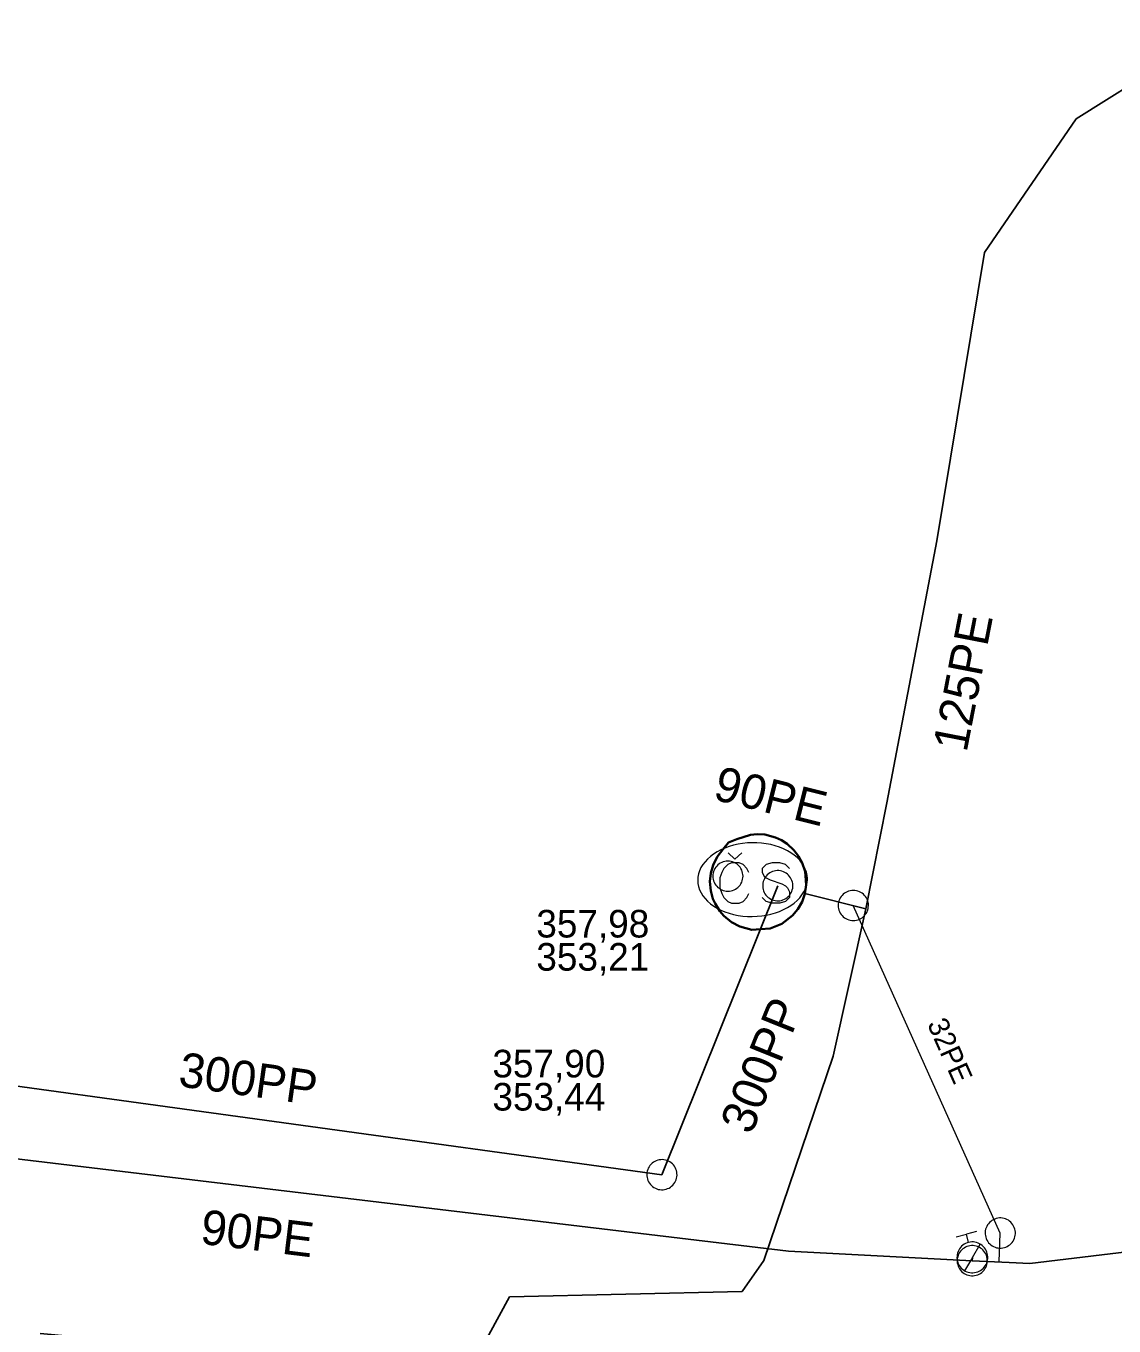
# Model space of a CAD drawing. Extents: x -741806 to -738704, y -1059275 to -1055387.
# Drawn here: x -740753.77 to -740722.25, y -1057687.05 to -1057649.38 of the extents above; entities that cross this region are included whole.
import ezdxf

# ---------------------------------------------------------------- set-up
doc = ezdxf.new("R2010")
doc.units = 0
doc.header["$LTSCALE"] = 0.4
for name, color, linetype, lineweight in [('11', 7, 'Continuous', 13), ('2', 7, 'Continuous', 25), ('21', 7, 'Continuous', 13), ('3', 7, 'Continuous', 13), ('45', 7, 'Continuous', 35), ('50', 7, 'Continuous', 13), ('51', 7, 'Continuous', 13), ('52', 7, 'Continuous', 25)]:
    doc.layers.add(name, color=color, linetype=linetype, lineweight=lineweight)
for name, color, linetype in [('5', 7, 'Continuous'), ('53', 7, 'Continuous'), ('54', 7, 'Continuous'), ('55', 7, 'Continuous')]:
    doc.layers.add(name, color=color, linetype=linetype)

msp = doc.modelspace()

# ---------------------------------------------------------------- linework, layer by layer
at = {"layer": '11'}
for q in [(-740733.428, -1057673.337), (-740733.036, -1057673.337)]:
    msp.add_line((-740733.232, -1057673.528), q, dxfattribs=at)
msp.add_lwpolyline([(-740731.135, -1057674.086), (-740731.143, -1057673.993), (-740731.163, -1057673.901), (-740731.194, -1057673.811), (-740731.237, -1057673.723), (-740731.292, -1057673.639), (-740731.357, -1057673.557), (-740731.432, -1057673.48), (-740731.517, -1057673.408), (-740731.612, -1057673.341), (-740731.714, -1057673.28), (-740731.824, -1057673.226), (-740731.941, -1057673.178), (-740732.064, -1057673.137), (-740732.192, -1057673.103), (-740732.324, -1057673.077), (-740732.459, -1057673.059), (-740732.596, -1057673.049), (-740732.734, -1057673.048), (-740732.872, -1057673.054), (-740733.009, -1057673.068), (-740733.143, -1057673.09), (-740733.274, -1057673.12), (-740733.402, -1057673.157), (-740733.524, -1057673.202), (-740733.64, -1057673.253), (-740733.749, -1057673.311), (-740733.85, -1057673.375), (-740733.943, -1057673.445), (-740734.027, -1057673.52), (-740734.1, -1057673.599), (-740734.164, -1057673.682), (-740734.216, -1057673.769), (-740734.257, -1057673.858), (-740734.287, -1057673.949), (-740734.305, -1057674.041), (-740734.311, -1057674.134), (-740734.305, -1057674.227), (-740734.286, -1057674.318), (-740734.257, -1057674.409), (-740734.215, -1057674.497), (-740734.162, -1057674.582), (-740734.099, -1057674.664), (-740734.025, -1057674.742), (-740733.941, -1057674.814), (-740733.848, -1057674.882), (-740733.746, -1057674.944), (-740733.637, -1057674.999), (-740733.521, -1057675.048), (-740733.399, -1057675.09), (-740733.271, -1057675.125), (-740733.14, -1057675.152), (-740733.005, -1057675.171), (-740732.868, -1057675.182), (-740732.731, -1057675.185), (-740732.593, -1057675.18), (-740732.456, -1057675.167), (-740732.321, -1057675.146), (-740732.189, -1057675.117), (-740732.061, -1057675.08), (-740731.938, -1057675.037), (-740731.822, -1057674.986), (-740731.711, -1057674.929), (-740731.609, -1057674.866), (-740731.515, -1057674.797), (-740731.43, -1057674.723), (-740731.355, -1057674.644), (-740731.29, -1057674.561), (-740731.236, -1057674.475), (-740731.193, -1057674.387), (-740731.162, -1057674.296), (-740731.143, -1057674.204), (-740731.135, -1057674.111)], close=True, dxfattribs=at)
for points in [[(-740732.828, -1057673.906), (-740732.884, -1057673.794), (-740732.996, -1057673.682), (-740733.108, -1057673.626), (-740733.33, -1057673.626), (-740733.439, -1057673.682), (-740733.551, -1057673.794), (-740733.615, -1057673.906), (-740733.671, -1057674.068), (-740733.671, -1057674.357), (-740733.615, -1057674.522), (-740733.551, -1057674.634), (-740733.439, -1057674.749), (-740733.33, -1057674.799), (-740733.108, -1057674.799), (-740732.996, -1057674.749), (-740732.884, -1057674.634), (-740732.828, -1057674.522)], [(-740731.655, -1057673.794), (-740731.767, -1057673.682), (-740731.932, -1057673.626), (-740732.156, -1057673.626), (-740732.324, -1057673.682), (-740732.442, -1057673.794), (-740732.442, -1057673.906), (-740732.389, -1057674.015), (-740732.324, -1057674.068), (-740732.21, -1057674.124), (-740731.876, -1057674.236), (-740731.767, -1057674.301), (-740731.711, -1057674.357), (-740731.655, -1057674.469), (-740731.655, -1057674.634), (-740731.767, -1057674.749), (-740731.932, -1057674.799), (-740732.156, -1057674.799), (-740732.324, -1057674.749), (-740732.442, -1057674.634)]]:
    msp.add_lwpolyline(points, dxfattribs=at)
at = {"layer": '2'}
for p, q in [((-740735.349, -1057682.666), (-740731.993, -1057674.294)), ((-740731.17, -1057674.524), (-740729.436, -1057674.959))]:
    msp.add_line(p, q, dxfattribs=at)
for points in [[(-740723.35, -1057652.071), (-740715.67, -1057647.25), (-740702.59, -1057629.575)], [(-740765.321, -1057634.66), (-740765.339, -1057637.145), (-740765.221, -1057649.531), (-740765.019, -1057662.11), (-740765.083, -1057671.477), (-740757.826, -1057679.575), (-740735.349, -1057682.666)], [(-740753.366, -1057687.272), (-740740.964, -1057688.405), (-740739.761, -1057686.21), (-740733.024, -1057686.05), (-740732.395, -1057685.151), (-740730.385, -1057679.235), (-740729.436, -1057674.959), (-740728.829, -1057671.892), (-740727.385, -1057664.297), (-740726.006, -1057655.95), (-740723.35, -1057652.071)]]:
    msp.add_lwpolyline(points, dxfattribs=at)
at = {"layer": '21'}
msp.add_lwpolyline([(-740725.581, -1057685.195), (-740725.546, -1057684.358), (-740729.804, -1057674.867)], dxfattribs=at)
at = {"layer": '3'}
for points in [[(-740732.999, -1057674.015), (-740733.002, -1057673.97), (-740733.009, -1057673.925), (-740733.021, -1057673.88), (-740733.037, -1057673.838), (-740733.058, -1057673.797), (-740733.083, -1057673.758), (-740733.112, -1057673.723), (-740733.144, -1057673.69), (-740733.18, -1057673.662), (-740733.218, -1057673.637), (-740733.259, -1057673.616), (-740733.302, -1057673.599), (-740733.346, -1057673.588), (-740733.391, -1057673.58), (-740733.437, -1057673.578), (-740733.483, -1057673.58), (-740733.528, -1057673.588), (-740733.572, -1057673.599), (-740733.615, -1057673.616), (-740733.656, -1057673.637), (-740733.694, -1057673.662), (-740733.729, -1057673.69), (-740733.762, -1057673.723), (-740733.791, -1057673.758), (-740733.816, -1057673.797), (-740733.836, -1057673.838), (-740733.853, -1057673.88), (-740733.865, -1057673.925), (-740733.872, -1057673.97), (-740733.874, -1057674.016), (-740733.872, -1057674.061), (-740733.865, -1057674.106), (-740733.853, -1057674.151), (-740733.836, -1057674.194), (-740733.816, -1057674.234), (-740733.791, -1057674.273), (-740733.762, -1057674.308), (-740733.729, -1057674.341), (-740733.694, -1057674.369), (-740733.656, -1057674.394), (-740733.615, -1057674.415), (-740733.572, -1057674.432), (-740733.528, -1057674.444), (-740733.483, -1057674.451), (-740733.437, -1057674.453), (-740733.391, -1057674.451), (-740733.346, -1057674.444), (-740733.302, -1057674.432), (-740733.259, -1057674.415), (-740733.218, -1057674.394), (-740733.18, -1057674.369), (-740733.144, -1057674.341), (-740733.112, -1057674.308), (-740733.083, -1057674.273), (-740733.058, -1057674.234), (-740733.037, -1057674.193), (-740733.021, -1057674.151), (-740733.009, -1057674.106), (-740733.002, -1057674.061), (-740732.999, -1057674.016)], [(-740731.829, -1057673.887), (-740731.872, -1057673.873), (-740731.916, -1057673.863), (-740731.963, -1057673.857), (-740732.007, -1057673.857), (-740732.053, -1057673.861), (-740732.099, -1057673.869), (-740732.142, -1057673.883), (-740732.185, -1057673.901), (-740732.224, -1057673.924), (-740732.261, -1057673.95), (-740732.296, -1057673.98), (-740732.328, -1057674.014), (-740732.355, -1057674.05), (-740732.379, -1057674.089), (-740732.398, -1057674.131), (-740732.413, -1057674.175), (-740732.422, -1057674.219), (-740732.428, -1057674.264), (-740732.429, -1057674.31), (-740732.424, -1057674.356), (-740732.415, -1057674.401), (-740732.402, -1057674.444), (-740732.384, -1057674.487), (-740732.362, -1057674.527), (-740732.335, -1057674.564), (-740732.305, -1057674.598), (-740732.272, -1057674.63), (-740732.235, -1057674.657), (-740732.196, -1057674.681), (-740732.154, -1057674.7), (-740732.111, -1057674.715), (-740732.067, -1057674.725), (-740732.021, -1057674.73), (-740731.974, -1057674.731), (-740731.93, -1057674.727), (-740731.884, -1057674.718), (-740731.841, -1057674.704), (-740731.798, -1057674.686), (-740731.759, -1057674.664), (-740731.722, -1057674.638), (-740731.687, -1057674.608), (-740731.655, -1057674.574), (-740731.628, -1057674.538), (-740731.604, -1057674.499), (-740731.585, -1057674.457), (-740731.57, -1057674.413), (-740731.56, -1057674.369), (-740731.555, -1057674.324), (-740731.555, -1057674.277), (-740731.559, -1057674.231), (-740731.568, -1057674.187), (-740731.58, -1057674.143), (-740731.599, -1057674.101), (-740731.621, -1057674.061), (-740731.648, -1057674.023), (-740731.678, -1057673.989), (-740731.711, -1057673.958), (-740731.748, -1057673.93), (-740731.787, -1057673.907), (-740731.828, -1057673.888)], [(-740734.915, -1057682.726), (-740734.911, -1057682.681), (-740734.912, -1057682.635), (-740734.918, -1057682.589), (-740734.928, -1057682.545), (-740734.943, -1057682.502), (-740734.963, -1057682.46), (-740734.987, -1057682.421), (-740735.014, -1057682.384), (-740735.046, -1057682.351), (-740735.08, -1057682.321), (-740735.118, -1057682.295), (-740735.158, -1057682.272), (-740735.2, -1057682.255), (-740735.244, -1057682.241), (-740735.289, -1057682.233), (-740735.335, -1057682.229), (-740735.381, -1057682.231), (-740735.426, -1057682.235), (-740735.471, -1057682.246), (-740735.514, -1057682.262), (-740735.555, -1057682.281), (-740735.594, -1057682.304), (-740735.631, -1057682.332), (-740735.664, -1057682.363), (-740735.694, -1057682.398), (-740735.72, -1057682.436), (-740735.742, -1057682.476), (-740735.76, -1057682.519), (-740735.773, -1057682.562), (-740735.782, -1057682.607), (-740735.786, -1057682.652), (-740735.785, -1057682.698), (-740735.779, -1057682.744), (-740735.768, -1057682.789), (-740735.754, -1057682.831), (-740735.734, -1057682.873), (-740735.71, -1057682.912), (-740735.682, -1057682.949), (-740735.651, -1057682.982), (-740735.617, -1057683.012), (-740735.579, -1057683.038), (-740735.539, -1057683.061), (-740735.497, -1057683.079), (-740735.454, -1057683.092), (-740735.408, -1057683.1), (-740735.362, -1057683.104), (-740735.317, -1057683.103), (-740735.272, -1057683.097), (-740735.227, -1057683.087), (-740735.183, -1057683.071), (-740735.142, -1057683.052), (-740735.103, -1057683.029), (-740735.067, -1057683.001), (-740735.033, -1057682.97), (-740735.003, -1057682.935), (-740734.977, -1057682.897), (-740734.955, -1057682.857), (-740734.937, -1057682.814), (-740734.924, -1057682.771), (-740734.915, -1057682.727)]]:
    msp.add_lwpolyline(points, dxfattribs=at)
at = {"layer": '45'}
msp.add_lwpolyline([(-740732.061, -1057672.894), (-740732.367, -1057672.814), (-740732.586, -1057672.8), (-740732.78, -1057672.817), (-740733.175, -1057672.941), (-740733.416, -1057673.037), (-740733.584, -1057673.244), (-740733.747, -1057673.456), (-740733.867, -1057673.695), (-740733.934, -1057673.929), (-740733.958, -1057674.171), (-740733.934, -1057674.438), (-740733.869, -1057674.673), (-740733.81, -1057674.807), (-740733.668, -1057675.034), (-740733.556, -1057675.163), (-740733.331, -1057675.348), (-740733.094, -1057675.474), (-740732.741, -1057675.568), (-740732.496, -1057675.55), (-740732.209, -1057675.535), (-740731.871, -1057675.398), (-740731.562, -1057675.161), (-740731.408, -1057674.973), (-740731.288, -1057674.761), (-740731.206, -1057674.531), (-740731.168, -1057674.272), (-740731.202, -1057673.884), (-740731.286, -1057673.63), (-740731.391, -1057673.438), (-740731.524, -1057673.264), (-740731.721, -1057673.082), (-740731.885, -1057672.976)], close=True, dxfattribs=at)
at = {"layer": '50'}
for p, q in [((-740726.231, -1057684.309), (-740726.528, -1057684.387)), ((-740726.826, -1057684.464), (-740726.528, -1057684.387)), ((-740726.465, -1057684.629), (-740726.528, -1057684.387)), ((-740726.351, -1057685.062), (-740726.125, -1057684.681)), ((-740726.351, -1057685.062), (-740726.578, -1057685.448))]:
    msp.add_line(p, q, dxfattribs=at)
msp.add_lwpolyline([(-740725.921, -1057684.954), (-740725.936, -1057684.907), (-740725.952, -1057684.864), (-740725.976, -1057684.823), (-740726.004, -1057684.786), (-740726.032, -1057684.752), (-740726.069, -1057684.719), (-740726.105, -1057684.692), (-740726.146, -1057684.667), (-740726.188, -1057684.646), (-740726.232, -1057684.633), (-740726.278, -1057684.622), (-740726.324, -1057684.615), (-740726.371, -1057684.616), (-740726.418, -1057684.62), (-740726.463, -1057684.629), (-740726.507, -1057684.643), (-740726.549, -1057684.66), (-740726.59, -1057684.684), (-740726.628, -1057684.711), (-740726.665, -1057684.742), (-740726.695, -1057684.776), (-740726.724, -1057684.814), (-740726.747, -1057684.854), (-740726.767, -1057684.895), (-740726.783, -1057684.94), (-740726.794, -1057684.986), (-740726.798, -1057685.031), (-740726.8, -1057685.079), (-740726.794, -1057685.125), (-740726.788, -1057685.171), (-740726.773, -1057685.217), (-740726.754, -1057685.259), (-740726.732, -1057685.298), (-740726.705, -1057685.339), (-740726.674, -1057685.373), (-740726.64, -1057685.406), (-740726.602, -1057685.432), (-740726.563, -1057685.458), (-740726.518, -1057685.477), (-740726.475, -1057685.491), (-740726.428, -1057685.501), (-740726.383, -1057685.506), (-740726.338, -1057685.509), (-740726.288, -1057685.504), (-740726.243, -1057685.495), (-740726.199, -1057685.481), (-740726.157, -1057685.462), (-740726.115, -1057685.44), (-740726.077, -1057685.413), (-740726.041, -1057685.381), (-740726.01, -1057685.348), (-740725.981, -1057685.31), (-740725.958, -1057685.271), (-740725.938, -1057685.229), (-740725.925, -1057685.184), (-740725.912, -1057685.139), (-740725.907, -1057685.092), (-740725.908, -1057685.046), (-740725.912, -1057684.999)], close=True, dxfattribs=at)
at = {"layer": '51'}
for points in [[(-740729.982, -1057674.468), (-740730.022, -1057674.488), (-740730.06, -1057674.513), (-740730.096, -1057674.542), (-740730.128, -1057674.574), (-740730.157, -1057674.61), (-740730.182, -1057674.648), (-740730.202, -1057674.689), (-740730.219, -1057674.732), (-740730.23, -1057674.776), (-740730.238, -1057674.821), (-740730.24, -1057674.867), (-740730.238, -1057674.913), (-740730.231, -1057674.958), (-740730.219, -1057675.002), (-740730.202, -1057675.045), (-740730.181, -1057675.086), (-740730.156, -1057675.124), (-740730.127, -1057675.16), (-740730.094, -1057675.192), (-740730.058, -1057675.221), (-740730.02, -1057675.245), (-740729.98, -1057675.267), (-740729.936, -1057675.282), (-740729.893, -1057675.294), (-740729.847, -1057675.301), (-740729.801, -1057675.304), (-740729.756, -1057675.301), (-740729.71, -1057675.294), (-740729.666, -1057675.282), (-740729.623, -1057675.266), (-740729.583, -1057675.244), (-740729.545, -1057675.22), (-740729.509, -1057675.19), (-740729.477, -1057675.158), (-740729.448, -1057675.122), (-740729.423, -1057675.084), (-740729.403, -1057675.043), (-740729.386, -1057675), (-740729.375, -1057674.956), (-740729.368, -1057674.911), (-740729.365, -1057674.865), (-740729.367, -1057674.819), (-740729.375, -1057674.774), (-740729.386, -1057674.73), (-740729.403, -1057674.687), (-740729.424, -1057674.646), (-740729.45, -1057674.608), (-740729.478, -1057674.572), (-740729.511, -1057674.54), (-740729.547, -1057674.511), (-740729.585, -1057674.487), (-740729.625, -1057674.466), (-740729.669, -1057674.45), (-740729.713, -1057674.438), (-740729.758, -1057674.431), (-740729.804, -1057674.428), (-740729.849, -1057674.431), (-740729.895, -1057674.439), (-740729.939, -1057674.451), (-740729.981, -1057674.467)], [(-740725.527, -1057683.921), (-740725.572, -1057683.921), (-740725.617, -1057683.926), (-740725.663, -1057683.936), (-740725.705, -1057683.951), (-740725.747, -1057683.97), (-740725.787, -1057683.993), (-740725.823, -1057684.021), (-740725.858, -1057684.051), (-740725.887, -1057684.086), (-740725.914, -1057684.123), (-740725.936, -1057684.163), (-740725.955, -1057684.205), (-740725.969, -1057684.249), (-740725.978, -1057684.294), (-740725.982, -1057684.339), (-740725.982, -1057684.386), (-740725.976, -1057684.431), (-740725.966, -1057684.475), (-740725.951, -1057684.519), (-740725.932, -1057684.561), (-740725.908, -1057684.6), (-740725.882, -1057684.637), (-740725.85, -1057684.67), (-740725.816, -1057684.701), (-740725.778, -1057684.727), (-740725.738, -1057684.75), (-740725.697, -1057684.768), (-740725.653, -1057684.781), (-740725.608, -1057684.79), (-740725.562, -1057684.795), (-740725.517, -1057684.794), (-740725.472, -1057684.789), (-740725.426, -1057684.779), (-740725.384, -1057684.765), (-740725.342, -1057684.745), (-740725.302, -1057684.722), (-740725.266, -1057684.694), (-740725.231, -1057684.664), (-740725.202, -1057684.629), (-740725.175, -1057684.592), (-740725.153, -1057684.552), (-740725.134, -1057684.51), (-740725.121, -1057684.466), (-740725.111, -1057684.421), (-740725.107, -1057684.376), (-740725.107, -1057684.33), (-740725.114, -1057684.284), (-740725.123, -1057684.24), (-740725.138, -1057684.196), (-740725.157, -1057684.154), (-740725.181, -1057684.115), (-740725.207, -1057684.078), (-740725.239, -1057684.045), (-740725.273, -1057684.014), (-740725.311, -1057683.988), (-740725.351, -1057683.965), (-740725.392, -1057683.947), (-740725.436, -1057683.934), (-740725.481, -1057683.925), (-740725.526, -1057683.921)], [(-740725.92, -1057685.18), (-740725.92, -1057685.135), (-740725.925, -1057685.09), (-740725.934, -1057685.044), (-740725.948, -1057685.002), (-740725.967, -1057684.96), (-740725.99, -1057684.919), (-740726.017, -1057684.883), (-740726.047, -1057684.848), (-740726.082, -1057684.819), (-740726.119, -1057684.792), (-740726.158, -1057684.769), (-740726.201, -1057684.749), (-740726.244, -1057684.735), (-740726.288, -1057684.726), (-740726.334, -1057684.722), (-740726.38, -1057684.721), (-740726.426, -1057684.726), (-740726.47, -1057684.736), (-740726.514, -1057684.75), (-740726.556, -1057684.769), (-740726.595, -1057684.792), (-740726.633, -1057684.819), (-740726.666, -1057684.85), (-740726.697, -1057684.883), (-740726.724, -1057684.921), (-740726.747, -1057684.961), (-740726.765, -1057685.002), (-740726.779, -1057685.046), (-740726.789, -1057685.091), (-740726.794, -1057685.137), (-740726.793, -1057685.182), (-740726.789, -1057685.227), (-740726.779, -1057685.273), (-740726.765, -1057685.315), (-740726.746, -1057685.357), (-740726.723, -1057685.398), (-740726.696, -1057685.434), (-740726.666, -1057685.469), (-740726.631, -1057685.498), (-740726.595, -1057685.525), (-740726.555, -1057685.548), (-740726.513, -1057685.568), (-740726.469, -1057685.581), (-740726.425, -1057685.591), (-740726.379, -1057685.595), (-740726.333, -1057685.596), (-740726.287, -1057685.59), (-740726.243, -1057685.581), (-740726.199, -1057685.567), (-740726.157, -1057685.548), (-740726.118, -1057685.525), (-740726.08, -1057685.498), (-740726.047, -1057685.467), (-740726.016, -1057685.434), (-740725.989, -1057685.396), (-740725.966, -1057685.356), (-740725.948, -1057685.315), (-740725.934, -1057685.271), (-740725.924, -1057685.226), (-740725.92, -1057685.181)]]:
    msp.add_lwpolyline(points, dxfattribs=at)
at = {"layer": '52'}
msp.add_line((-740726.357, -1057685.158), (-740726.353, -1057685.058), dxfattribs=at)
msp.add_lwpolyline([(-740767.701, -1057643.739), (-740767.68, -1057653.215), (-740767.688, -1057656.303), (-740767.625, -1057659.884), (-740767.56, -1057663.571), (-740767.412, -1057673.085), (-740759.954, -1057681.499), (-740731.682, -1057684.887), (-740726.357, -1057685.158), (-740725.284, -1057685.21), (-740724.688, -1057685.239), (-740698.842, -1057682.125), (-740692.883, -1057686.829)], dxfattribs=at)

# ---------------------------------------------------------------- texts
at = {"layer": '5'}
for s, rotation, p in [('125PE ', 79, (-740726.521, -1057670.451)), ('90PE', 346, (-740733.9, -1057671.784)), ('300PP ', 68, (-740732.758, -1057681.538)), ('300PP ', 352, (-740749.386, -1057680.1))]:
    msp.add_text(s, height=1, rotation=rotation, dxfattribs=at).set_placement(p)
at = {"layer": '53'}
msp.add_text('90PE', height=1, rotation=353, dxfattribs=at).set_placement((-740748.751, -1057684.662))
at = {"layer": '54'}
msp.add_text('32PE', height=0.6, rotation=294, dxfattribs=at).set_placement((-740727.672, -1057678.295))
at = {"layer": '55'}
for s, p in [('357,98', (-740738.987, -1057675.794)), ('353,21', (-740738.987, -1057676.754)), ('357,90', (-740740.26, -1057679.848)), ('353,44', (-740740.26, -1057680.808))]:
    msp.add_text(s, height=0.8, dxfattribs=at).set_placement(p)

doc.saveas('drawing.dxf')
